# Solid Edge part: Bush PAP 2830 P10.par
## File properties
Title: PAP 2830 P10
Author: Dan
Comments: INA Bush  Sales Wayne Holton 082 552 5587   Elandsfontein 011 225 3000  www.ina.com
Template: Normal.par
Last saved by: Dan
Revision: 10
Application: Solid Edge
Material: steel
Density: 0 kg/mm^3
Accuracy: 0.99
Document Number: P52-007
Project Name: Piston Pump P52
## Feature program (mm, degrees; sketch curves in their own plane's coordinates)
sketch for "unnamed Protrusion 1" #1 plane through (0, 0, 0) normal (0, 0, 1) x-axis (1, 0, 0)
  circle centre (0, 0) radius 16
sketch for "unnamed Protrusion 1" #2 plane through (0, 0, 0) normal (0, 0, 1) x-axis (1, 0, 0)
  circle centre (0, 0) radius 14
extrude "unnamed Protrusion 1" add finite 30 along +normal
chamfer "Chamfer_1" setback 0.8
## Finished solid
Body 1: solid body, 8 faces, 8 edges, 0 vertices.
  Faces by surface: cone 4, cylinder 2, plane 2
  Edges by curve: circle 8
Bounding box of the edges (mm): 32.000 x 32.000 x 30.000, from (-16, -16, 0) to (16, 16, 30).
Cylindrical faces by radius (mm): R14 x1, R16 x1
Conical faces (half-angle, radius in mm at the cone's reference point): 45 deg R14 x1, 45 deg R14.8 x1, 45 deg R15.2 x1, 45 deg R16 x1
Planar faces by outward normal: +z 1, -z 1
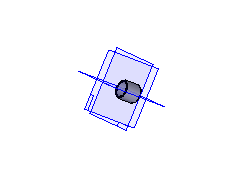
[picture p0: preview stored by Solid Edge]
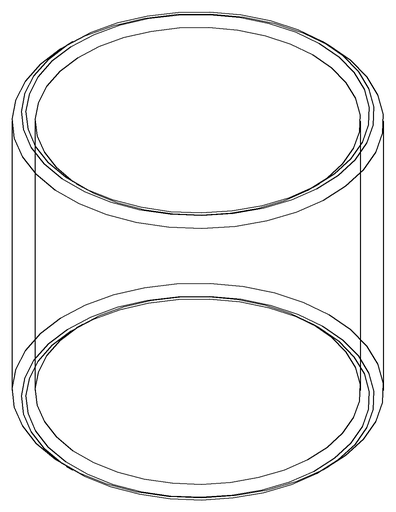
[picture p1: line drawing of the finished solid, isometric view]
